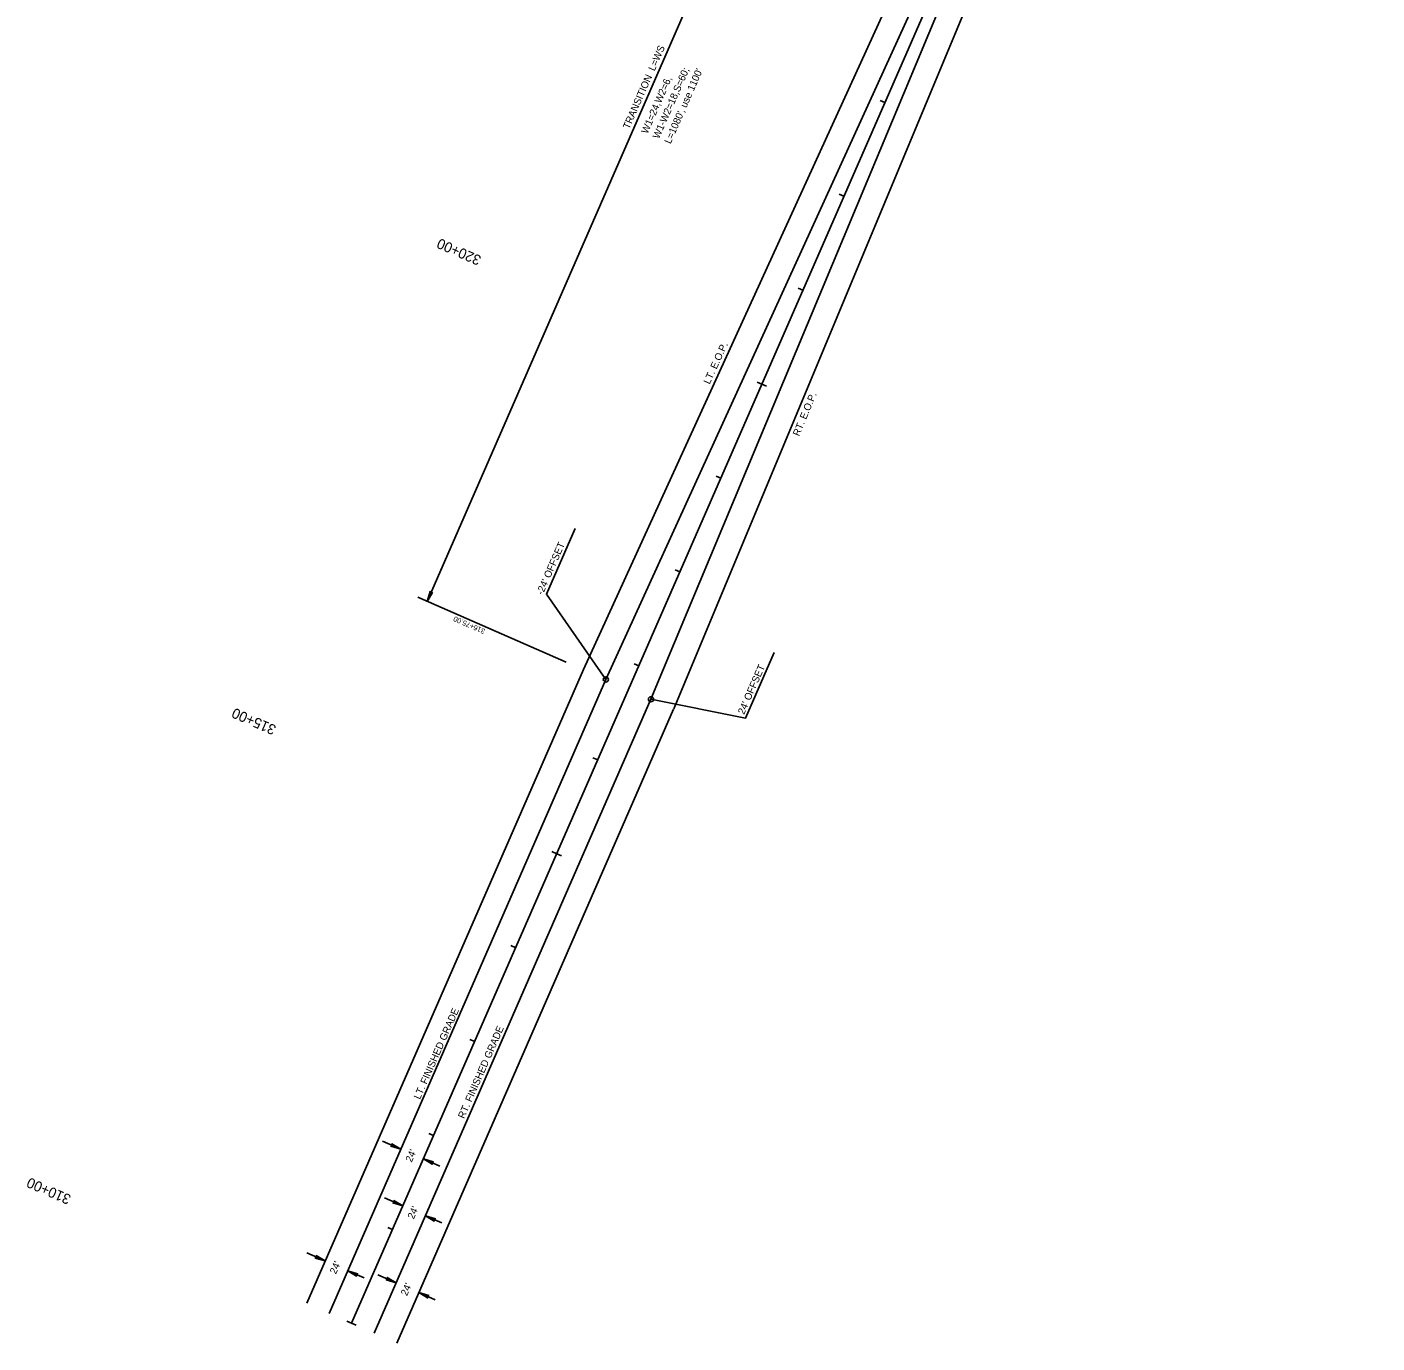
# Model space of a CAD drawing. Extents: x 2457443 to 2458788, y 602018 to 604471.
# Drawn here: x 2457443 to 2458760, y 602018 to 603303 of the extents above; entities that cross this region are included whole.
import ezdxf

# ---------------------------------------------------------------- set-up
doc = ezdxf.new("R2010")
doc.units = 0
for name, color, linetype in [('DESIGN - CENTERLINE - Proposed', 7, 'Continuous'), ('DESIGN - CENTERLINE - Proposed Curve Text', 7, 'Continuous'), ('DESIGN - CENTERLINE - Proposed Text', 7, 'Continuous'), ('DESIGN - TRANSPORTATION - Edge of Traveled Way', 7, 'Continuous'), ('DESIGN - TRANSPORTATION - Text', 7, 'Continuous'), ('SURVEY - CENTERLINE - Preliminary', 7, 'Continuous')]:
    doc.layers.add(name, color=color, linetype=linetype)

msp = doc.modelspace()

# ---------------------------------------------------------------- linework, layer by layer
at = {"layer": 'DESIGN - CENTERLINE - Proposed'}
msp.add_line((2457759.6, 602037.7), (2458760.1, 604328.7), dxfattribs=at)
at = {"layer": 'DESIGN - CENTERLINE - Proposed Text'}
for p, q in [((2458279.8, 603229), (2458275.3, 603231)), ((2458239.8, 603137.4), (2458235.2, 603139.4)), ((2458199.8, 603045.7), (2458195.2, 603047.7)), ((2458159.8, 602954.1), (2458155.2, 602956.1)), ((2458164.4, 602952.1), (2458159.8, 602954.1)), ((2458119.8, 602862.4), (2458115.2, 602864.4)), ((2458079.8, 602770.8), (2458075.2, 602772.8)), ((2458039.7, 602679.2), (2458035.2, 602681.2)), ((2457999.7, 602587.5), (2457995.1, 602589.5)), ((2457959.7, 602495.9), (2457955.1, 602497.9)), ((2457964.3, 602493.9), (2457959.7, 602495.9)), ((2457964.3, 602493.9), (2457959.7, 602495.9)), ((2457919.7, 602404.2), (2457915.1, 602406.2)), ((2457879.7, 602312.6), (2457875.1, 602314.6)), ((2457839.6, 602220.9), (2457835.1, 602222.9)), ((2457799.6, 602129.3), (2457795, 602131.3)), ((2457759.6, 602037.7), (2457755, 602039.7)), ((2457764.2, 602035.7), (2457759.6, 602037.7)), ((2457764.2, 602035.7), (2457759.6, 602037.7))]:
    msp.add_line(p, q, dxfattribs=at)
at = {"layer": 'DESIGN - TRANSPORTATION - Edge of Traveled Way'}
for p, q in [((2457985.9, 602675.8), (2458434.6, 603658.4)), ((2458073.9, 602637.4), (2458489.6, 603634.4)), ((2457715.8, 602057.2), (2457985.9, 602675.8)), ((2457737.6, 602047.3), (2458007.7, 602665.9)), ((2457781.6, 602028.1), (2458051.7, 602646.6)), ((2457803.6, 602018.4), (2458073.7, 602637))]:
    msp.add_line(p, q, dxfattribs=at)
for points in [[(2458007.7, 602665.9), (2458464.4, 603666.7), (2458489.9, 603710.2)], [(2458051.7, 602646.6), (2458475.4, 603661.9), (2458489.9, 603710.2)]]:
    msp.add_lwpolyline(points, dxfattribs=at)
msp.add_circle((2458007.7, 602665.9), 2.5, dxfattribs=at)
at = {"layer": 'DESIGN - TRANSPORTATION - Text'}
for p, q in [((2457833.2, 602742.1), (2458273.4, 603750.1)), ((2457968.8, 602682.9), (2457824.1, 602746.1)), ((2457807.6, 602207.6), (2457789.6, 602215.5)), ((2457845.7, 602191), (2457829.6, 602198)), ((2457809.6, 602152.2), (2457791.6, 602160.1)), ((2457847.7, 602135.6), (2457831.6, 602142.6)), ((2457733.8, 602098.5), (2457715.8, 602106.3)), ((2457771.8, 602081.9), (2457755.8, 602088.9)), ((2457803.1, 602077.3), (2457785.1, 602085.1)), ((2457841.1, 602060.7), (2457825.1, 602067.7))]:
    msp.add_line(p, q, dxfattribs=at)
for points in [[(2458007.7, 602665.9), (2457949.7, 602749.1), (2457977.7, 602813.3)], [(2457833.2, 602742.1), (2457836.1, 602751.8), (2457836.7, 602750.1), (2457838.5, 602750.7), (2457833.2, 602742.1)], [(2458051.7, 602646.6), (2458144, 602628.2), (2458172, 602692.3)]]:
    msp.add_lwpolyline(points, dxfattribs=at)
msp.add_lwpolyline([(2457833.2, 602742.1), (2457836.1, 602751.8), (2457836.7, 602750.1), (2457838.5, 602750.7)], close=True, dxfattribs=at)
msp.add_circle((2458051.7, 602646.6), 2.5, dxfattribs=at)
at = {"layer": 'SURVEY - CENTERLINE - Preliminary'}
for points in [[(2457807.6, 602207.6), (2457797.9, 602210.5), (2457799.6, 602211.1), (2457799, 602212.8)], [(2457829.6, 602198), (2457839.3, 602195.2), (2457837.7, 602194.5), (2457838.3, 602192.8)], [(2457809.6, 602152.2), (2457799.9, 602155.1), (2457801.6, 602155.7), (2457800.9, 602157.4)], [(2457831.6, 602142.6), (2457841.3, 602139.7), (2457839.6, 602139.1), (2457840.3, 602137.4)], [(2457733.8, 602098.5), (2457724.1, 602101.3), (2457725.8, 602102), (2457725.1, 602103.7)], [(2457755.8, 602088.9), (2457765.5, 602086), (2457763.8, 602085.4), (2457764.5, 602083.7)], [(2457803.1, 602077.3), (2457793.4, 602080.2), (2457795.1, 602080.8), (2457794.4, 602082.5)], [(2457825.1, 602067.7), (2457834.8, 602064.8), (2457833.1, 602064.2), (2457833.8, 602062.5)]]:
    msp.add_lwpolyline(points, close=True, dxfattribs=at)
for points in [[(2457807.6, 602207.6), (2457797.9, 602210.5), (2457799.6, 602211.1), (2457799, 602212.8), (2457807.6, 602207.6)], [(2457829.6, 602198), (2457839.3, 602195.2), (2457837.7, 602194.5), (2457838.3, 602192.8), (2457829.6, 602198)], [(2457809.6, 602152.2), (2457799.9, 602155.1), (2457801.6, 602155.7), (2457800.9, 602157.4), (2457809.6, 602152.2)], [(2457831.6, 602142.6), (2457841.3, 602139.7), (2457839.6, 602139.1), (2457840.3, 602137.4), (2457831.6, 602142.6)], [(2457733.8, 602098.5), (2457724.1, 602101.3), (2457725.8, 602102), (2457725.1, 602103.7), (2457733.8, 602098.5)], [(2457755.8, 602088.9), (2457765.5, 602086), (2457763.8, 602085.4), (2457764.5, 602083.7), (2457755.8, 602088.9)], [(2457803.1, 602077.3), (2457793.4, 602080.2), (2457795.1, 602080.8), (2457794.4, 602082.5), (2457803.1, 602077.3)], [(2457825.1, 602067.7), (2457834.8, 602064.8), (2457833.1, 602064.2), (2457833.8, 602062.5), (2457825.1, 602067.7)]]:
    msp.add_lwpolyline(points, dxfattribs=at)

# ---------------------------------------------------------------- texts
at = {"layer": 'DESIGN - CENTERLINE - Proposed Curve Text'}
msp.add_text('316+75.00', height=5, rotation=156.4105, dxfattribs=at).set_placement((2457890.4, 602714.7))
at = {"layer": 'DESIGN - CENTERLINE - Proposed Text'}
for s, p in [('320+00', (2457886.9, 603078.7)), ('315+00', (2457686.8, 602620.5)), ('310+00', (2457486.7, 602162.3))]:
    msp.add_text(s, height=10, rotation=156.4105, dxfattribs=at).set_placement(p)
at = {"layer": 'DESIGN - TRANSPORTATION - Text'}
for s, rotation, p in [('TRANSITION  L=WS', 66.4105, (2458030.4, 603202.4)), ('W1-W2=18,S=60;  ', 66.4105, (2458059.5, 603192.9)), ("L=1080', use 1100'", 66.4105, (2458070.8, 603188)), ('W1=24,W2=6,', 66.4105, (2458048.3, 603197.8)), ('LT. E.O.P.', 65.4556, (2458108.9, 602953.5)), ('RT. E.O.P.', 67.3653, (2458196.2, 602902.8)), ("-24' OFFSET", 66.4105, (2457946, 602747.8)), ("24' OFFSET", 66.4105, (2458142.5, 602631.2)), ('LT. FINISHED GRADE', 66.4105, (2457826.3, 602255.6)), ('RT. FINISHED GRADE', 66.4105, (2457869.4, 602236.8)), ("24'", 66.4105, (2457818.2, 602194.3)), ("24'", 66.4105, (2457820.2, 602138.8)), ("24'", 66.4105, (2457744.3, 602085.1)), ("24'", 66.4105, (2457813.6, 602063.9))]:
    msp.add_text(s, height=7, rotation=rotation, dxfattribs=at).set_placement(p)

doc.saveas('drawing.dxf')
